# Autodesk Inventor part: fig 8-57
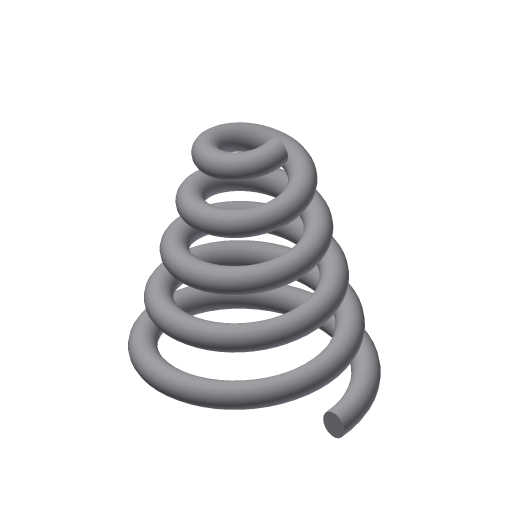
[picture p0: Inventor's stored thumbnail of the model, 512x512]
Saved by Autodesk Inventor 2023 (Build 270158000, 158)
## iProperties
Created: 2002-01
Part Number: fig 8-57
Document SubType Name: Modeling
Designer: CADSoft
Density: 1 g/cm^3
Material: Generic
Appearance: Default
Control State: 0
Master: False
Checked Out: False
Shininess: 77.0
Length Units: 11269
Angle Units: 11279
Time Units: 11290
Mass Units: 11283
Length Display Precision: 3
Angle Display Precision: 2
Density: 0.0
Volumn: 0.0
Area: 0.0
PropertySet Name: Model Information
Author: CADSoft
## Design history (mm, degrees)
sketch "Sketch2"
  geometry: C1 r 2.5 at (-19.895, -0.092)
  constraints: 1 centre point
  dimensions: "d0" = 5 diameter of C1
coil "Coil5" sketch "Sketch2" pitch "d35" = 10; turns "d37" = 5; dims "d36" = 10, "d38" = -15 deg, angle "d39" = 90 deg, angle "d40" = 90 deg, "d41" = 0, "d42" = 0
body "Solid1"
